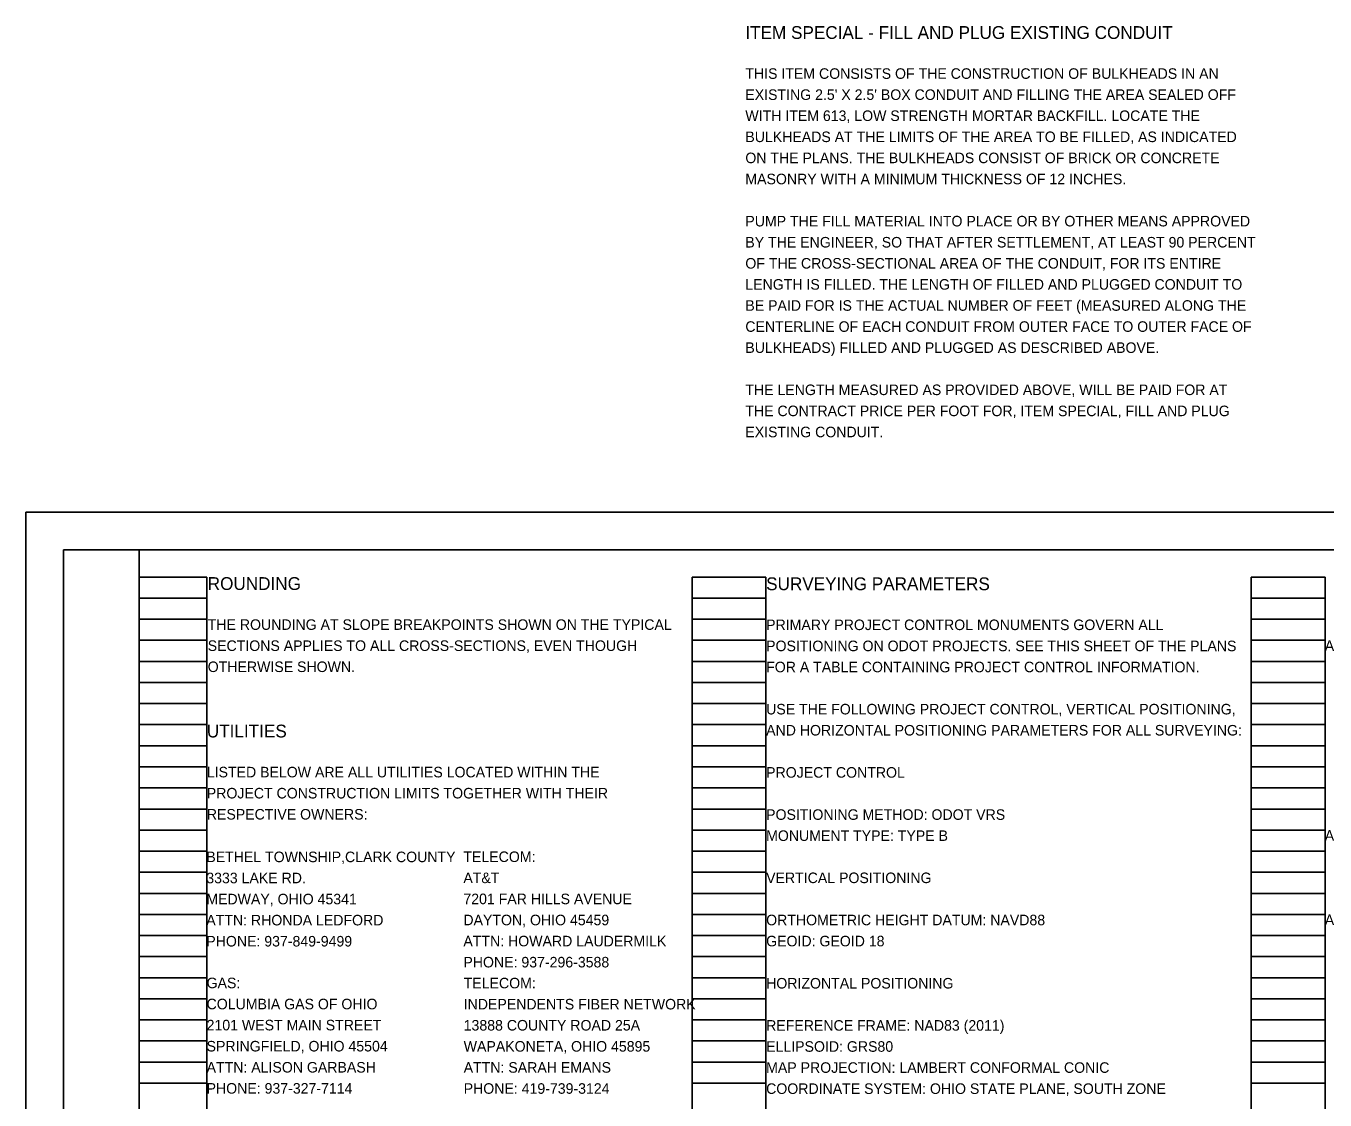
# Model space of a CAD drawing. Extents: x 0 to 52.6, y 0 to 28.5.
# Drawn here: x 0 to 17.24, y 14.19 to 28.46 of the extents above; entities that cross this region are included whole.
import ezdxf

# ---------------------------------------------------------------- set-up
doc = ezdxf.new("R2010")
doc.units = 0
for name, color, linetype in [('SH_Border', 7, 'Continuous'), ('SH_Cut_Line', 7, 'Continuous'), ('SH_Data', 7, 'Continuous'), ('SH_Text', 7, 'Continuous')]:
    doc.layers.add(name, color=color, linetype=linetype)

msp = doc.modelspace()

# ---------------------------------------------------------------- linework, layer by layer
at = {"layer": 'SH_Border'}
for points in [[(0.5, 21.5), (1.5, 21.5), (1.5, 0.5), (0.5, 0.5)], [(1.5, 21.5), (33.5, 21.5), (33.5, 0.5), (1.5, 0.5)]]:
    msp.add_lwpolyline(points, close=True, dxfattribs=at)
at = {"layer": 'SH_Cut_Line'}
msp.add_lwpolyline([(0, 0), (34, 0), (34, 22), (0, 22)], close=True, dxfattribs=at)
at = {"layer": 'SH_Data'}
for p, q in [((1.5, 0.98), (1.5, 21.14)), ((1.5, 21.14), (2.4, 21.14)), ((2.4, 0.98), (2.4, 21.14)), ((8.84, 0.98), (8.84, 21.14)), ((8.84, 21.14), (9.82, 21.14)), ((9.82, 0.98), (9.82, 21.14)), ((16.26, 0.98), (16.26, 21.14)), ((16.26, 21.14), (17.24, 21.14)), ((17.24, 0.98), (17.24, 21.14)), ((1.5, 20.86), (2.4, 20.86)), ((8.84, 20.86), (9.82, 20.86)), ((16.26, 20.86), (17.24, 20.86)), ((1.5, 20.58), (2.4, 20.58)), ((8.84, 20.58), (9.82, 20.58)), ((16.26, 20.58), (17.24, 20.58)), ((1.5, 20.3), (2.4, 20.3)), ((8.84, 20.3), (9.82, 20.3)), ((16.26, 20.3), (17.24, 20.3)), ((1.5, 20.02), (2.4, 20.02)), ((8.84, 20.02), (9.82, 20.02)), ((16.26, 20.02), (17.24, 20.02)), ((1.5, 19.74), (2.4, 19.74)), ((8.84, 19.74), (9.82, 19.74)), ((16.26, 19.74), (17.24, 19.74)), ((1.5, 19.46), (2.4, 19.46)), ((8.84, 19.46), (9.82, 19.46)), ((16.26, 19.46), (17.24, 19.46)), ((1.5, 19.18), (2.4, 19.18)), ((8.84, 19.18), (9.82, 19.18)), ((16.26, 19.18), (17.24, 19.18)), ((1.5, 18.9), (2.4, 18.9)), ((8.84, 18.9), (9.82, 18.9)), ((16.26, 18.9), (17.24, 18.9)), ((1.5, 18.62), (2.4, 18.62)), ((8.84, 18.62), (9.82, 18.62)), ((16.26, 18.62), (17.24, 18.62)), ((1.5, 18.34), (2.4, 18.34)), ((8.84, 18.34), (9.82, 18.34)), ((16.26, 18.34), (17.24, 18.34)), ((1.5, 18.06), (2.4, 18.06)), ((8.84, 18.06), (9.82, 18.06)), ((16.26, 18.06), (17.24, 18.06)), ((1.5, 17.78), (2.4, 17.78)), ((8.84, 17.78), (9.82, 17.78)), ((16.26, 17.78), (17.24, 17.78)), ((1.5, 17.5), (2.4, 17.5)), ((8.84, 17.5), (9.82, 17.5)), ((16.26, 17.5), (17.24, 17.5)), ((1.5, 17.22), (2.4, 17.22)), ((8.84, 17.22), (9.82, 17.22)), ((16.26, 17.22), (17.24, 17.22)), ((1.5, 16.94), (2.4, 16.94)), ((8.84, 16.94), (9.82, 16.94)), ((16.26, 16.94), (17.24, 16.94)), ((1.5, 16.66), (2.4, 16.66)), ((8.84, 16.66), (9.82, 16.66)), ((16.26, 16.66), (17.24, 16.66)), ((1.5, 16.38), (2.4, 16.38)), ((8.84, 16.38), (9.82, 16.38)), ((16.26, 16.38), (17.24, 16.38)), ((1.5, 16.1), (2.4, 16.1)), ((8.84, 16.1), (9.82, 16.1)), ((16.26, 16.1), (17.24, 16.1)), ((1.5, 15.82), (2.4, 15.82)), ((8.84, 15.82), (9.82, 15.82)), ((16.26, 15.82), (17.24, 15.82)), ((1.5, 15.54), (2.4, 15.54)), ((8.84, 15.54), (9.82, 15.54)), ((16.26, 15.54), (17.24, 15.54)), ((1.5, 15.26), (2.4, 15.26)), ((8.84, 15.26), (9.82, 15.26)), ((16.26, 15.26), (17.24, 15.26)), ((1.5, 14.98), (2.4, 14.98)), ((8.84, 14.98), (9.82, 14.98)), ((16.26, 14.98), (17.24, 14.98)), ((1.5, 14.7), (2.4, 14.7)), ((8.84, 14.7), (9.82, 14.7)), ((16.26, 14.7), (17.24, 14.7)), ((1.5, 14.42), (2.4, 14.42)), ((8.84, 14.42), (9.82, 14.42)), ((16.26, 14.42), (17.24, 14.42))]:
    msp.add_line(p, q, dxfattribs=at)

# ---------------------------------------------------------------- texts
at = {"layer": 'SH_Text'}
for s, height, p in [('ITEM SPECIAL - FILL AND PLUG EXISTING CONDUIT', 0.17, (9.547, 28.287)), ('THIS ITEM CONSISTS OF THE CONSTRUCTION OF BULKHEADS IN AN ', 0.14, (9.547, 27.757)), ("EXISTING 2.5' X 2.5' BOX CONDUIT AND FILLING THE AREA SEALED OFF ", 0.14, (9.547, 27.477)), ('WITH ITEM 613, LOW STRENGTH MORTAR BACKFILL. LOCATE THE ', 0.14, (9.547, 27.197)), ('BULKHEADS AT THE LIMITS OF THE AREA TO BE FILLED, AS INDICATED ', 0.14, (9.547, 26.917)), ('ON THE PLANS. THE BULKHEADS CONSIST OF BRICK OR CONCRETE ', 0.14, (9.547, 26.637)), ('MASONRY WITH A MINIMUM THICKNESS OF 12 INCHES.', 0.14, (9.547, 26.357)), ('PUMP THE FILL MATERIAL INTO PLACE OR BY OTHER MEANS APPROVED ', 0.14, (9.547, 25.797)), ('BY THE ENGINEER, SO THAT AFTER SETTLEMENT, AT LEAST 90 PERCENT ', 0.14, (9.547, 25.517)), ('OF THE CROSS-SECTIONAL AREA OF THE CONDUIT, FOR ITS ENTIRE ', 0.14, (9.547, 25.237)), ('LENGTH IS FILLED. THE LENGTH OF FILLED AND PLUGGED CONDUIT TO ', 0.14, (9.547, 24.957)), ('BE PAID FOR IS THE ACTUAL NUMBER OF FEET (MEASURED ALONG THE ', 0.14, (9.547, 24.677)), ('CENTERLINE OF EACH CONDUIT FROM OUTER FACE TO OUTER FACE OF ', 0.14, (9.547, 24.397)), ('BULKHEADS) FILLED AND PLUGGED AS DESCRIBED ABOVE.', 0.14, (9.547, 24.117)), ('THE LENGTH MEASURED AS PROVIDED ABOVE, WILL BE PAID FOR AT ', 0.14, (9.547, 23.557)), ('THE CONTRACT PRICE PER FOOT FOR, ITEM SPECIAL, FILL AND PLUG ', 0.14, (9.547, 23.277)), ('EXISTING CONDUIT.', 0.14, (9.547, 22.997)), ('ROUNDING', 0.17, (2.412, 20.969)), ('SURVEYING PARAMETERS', 0.17, (9.823, 20.966)), ('THE ROUNDING AT SLOPE BREAKPOINTS SHOWN ON THE TYPICAL', 0.14, (2.412, 20.439)), ('PRIMARY PROJECT CONTROL MONUMENTS GOVERN ALL', 0.14, (9.823, 20.436)), ('SECTIONS APPLIES TO ALL CROSS-SECTIONS, EVEN THOUGH', 0.14, (2.412, 20.159)), ('POSITIONING ON ODOT PROJECTS. SEE THIS SHEET OF THE PLANS', 0.14, (9.823, 20.156)), ('ACCEPTANCE, PERFORM AN INSPECTION WITH REPRESENTATIVES', 0.14, (17.237, 20.159)), ('OTHERWISE SHOWN.', 0.14, (2.412, 19.879)), ('FOR A TABLE CONTAINING PROJECT CONTROL INFORMATION.', 0.14, (9.823, 19.876)), ('USE THE FOLLOWING PROJECT CONTROL, VERTICAL POSITIONING,', 0.14, (9.823, 19.316)), ('UTILITIES', 0.17, (2.4, 19.01)), ('AND HORIZONTAL POSITIONING PARAMETERS FOR ALL SURVEYING:', 0.14, (9.823, 19.036)), ('LISTED BELOW ARE ALL UTILITIES LOCATED WITHIN THE', 0.14, (2.4, 18.48)), ('PROJECT CONTROL', 0.14, (9.823, 18.476)), ('PROJECT CONSTRUCTION LIMITS TOGETHER WITH THEIR', 0.14, (2.4, 18.2)), ('RESPECTIVE OWNERS:', 0.14, (2.4, 17.92)), ('POSITIONING METHOD: ODOT VRS', 0.14, (9.823, 17.916)), ('MONUMENT TYPE: TYPE B', 0.14, (9.823, 17.636)), ('ABOVE-MENTIONED PARTIES ARE MAINTAINED AND LEFT IN A', 0.14, (17.237, 17.639)), ('BETHEL TOWNSHIP,CLARK COUNTY', 0.14, (2.393, 17.354)), ('TELECOM:', 0.14, (5.805, 17.356)), ('3333 LAKE RD.', 0.14, (2.393, 17.074)), ('AT&T', 0.14, (5.805, 17.076)), ('VERTICAL POSITIONING', 0.14, (9.823, 17.076)), ('MEDWAY, OHIO 45341', 0.14, (2.393, 16.794)), ('7201 FAR HILLS AVENUE', 0.14, (5.805, 16.796)), ('ATTN: RHONDA LEDFORD', 0.14, (2.393, 16.514)), ('DAYTON, OHIO 45459', 0.14, (5.805, 16.516)), ('ORTHOMETRIC HEIGHT DATUM: NAVD88', 0.14, (9.823, 16.516)), ('AS DIRECTED AND APPROVED BY THE ENGINEER.', 0.14, (17.237, 16.519)), ('PHONE: 937-849-9499', 0.14, (2.393, 16.234)), ('ATTN: HOWARD LAUDERMILK', 0.14, (5.805, 16.236)), ('GEOID: GEOID 18', 0.14, (9.823, 16.236)), ('PHONE: 937-296-3588', 0.14, (5.805, 15.956)), ('GAS:', 0.14, (2.397, 15.68)), ('TELECOM:', 0.14, (5.809, 15.678)), ('HORIZONTAL POSITIONING', 0.14, (9.823, 15.676)), ('COLUMBIA GAS OF OHIO', 0.14, (2.397, 15.4)), ('INDEPENDENTS FIBER NETWORK', 0.14, (5.809, 15.398)), ('2101 WEST MAIN STREET', 0.14, (2.397, 15.12)), ('13888 COUNTY ROAD 25A', 0.14, (5.809, 15.118)), ('REFERENCE FRAME: NAD83 (2011)', 0.14, (9.823, 15.116)), ('SPRINGFIELD, OHIO 45504', 0.14, (2.397, 14.84)), ('WAPAKONETA, OHIO 45895', 0.14, (5.809, 14.838)), ('ELLIPSOID: GRS80', 0.14, (9.823, 14.836)), ('ATTN: ALISON GARBASH', 0.14, (2.397, 14.56)), ('ATTN: SARAH EMANS', 0.14, (5.809, 14.558)), ('MAP PROJECTION: LAMBERT CONFORMAL CONIC', 0.14, (9.823, 14.556)), ('PHONE: 937-327-7114', 0.14, (2.397, 14.28)), ('PHONE: 419-739-3124', 0.14, (5.809, 14.278)), ('COORDINATE SYSTEM: OHIO STATE PLANE, SOUTH ZONE', 0.14, (9.823, 14.276))]:
    msp.add_text(s, height=height, dxfattribs=at).set_placement(p)

doc.saveas('drawing.dxf')
